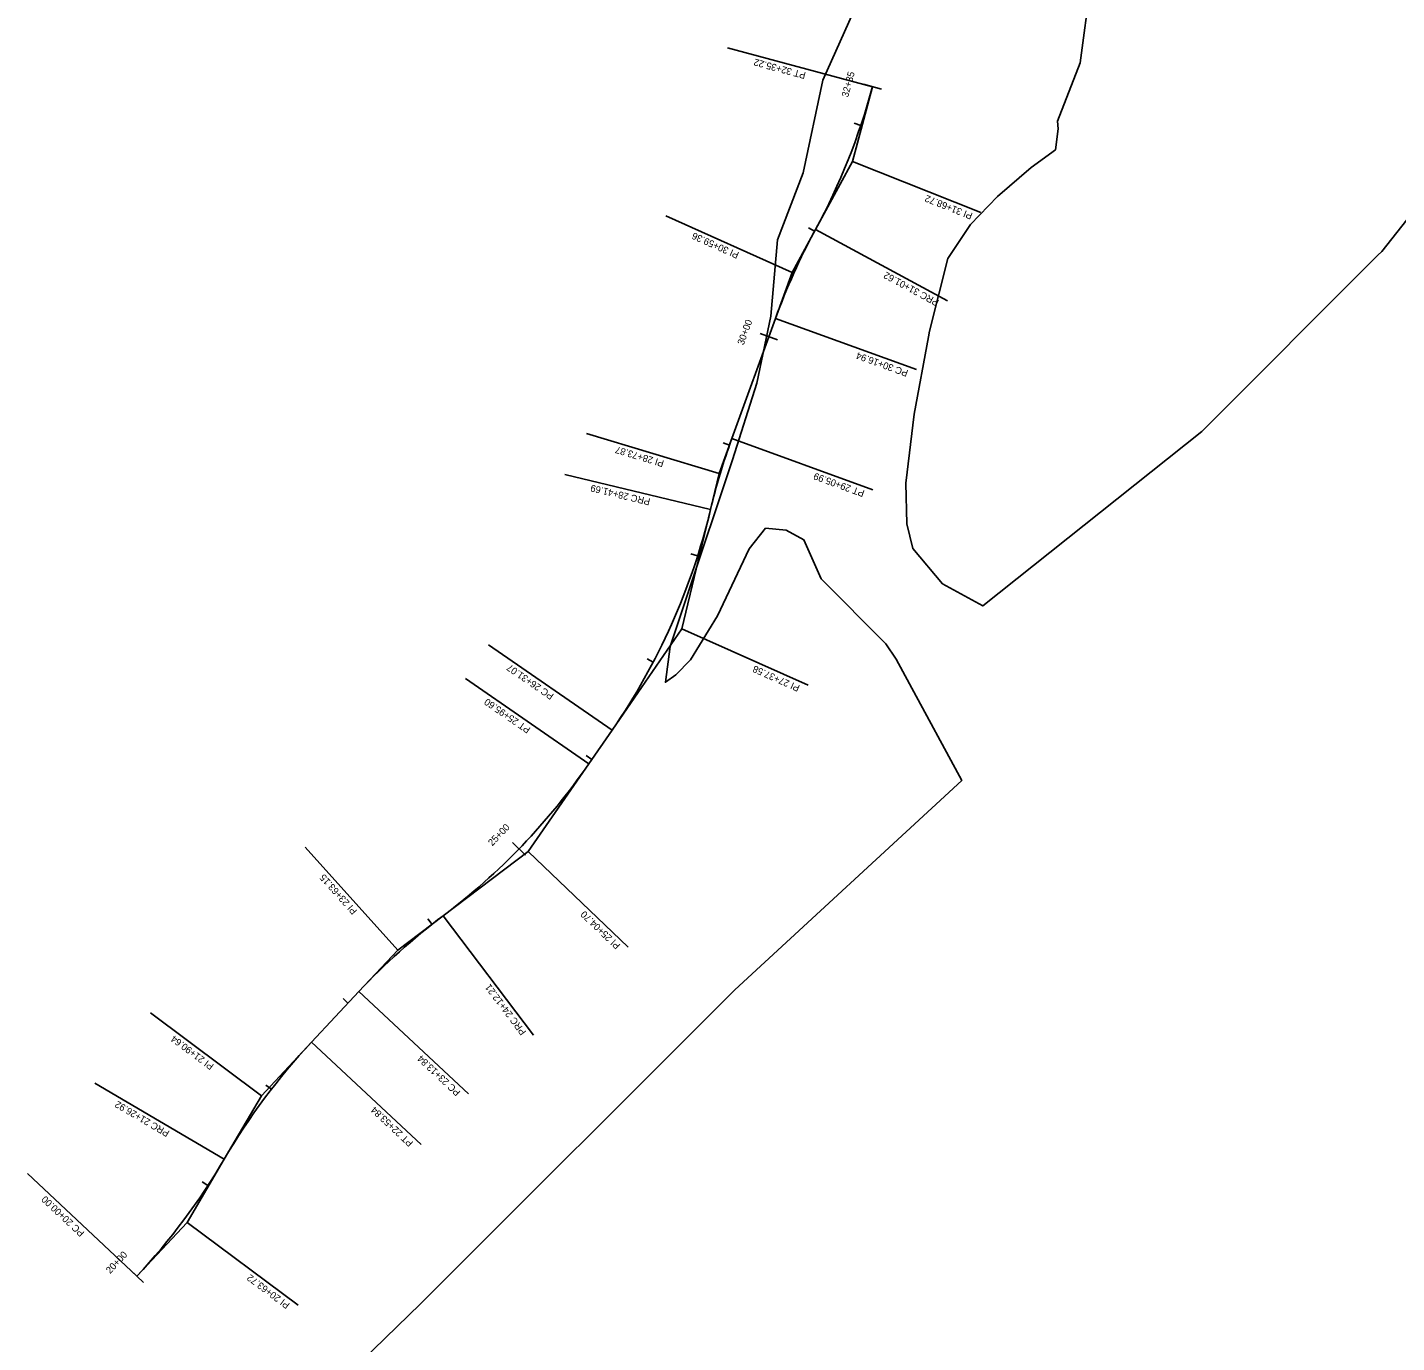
# Model space of a CAD drawing. Extents: x 983486 to 994833, y 1835619 to 1844358.
# Drawn here: x 991845 to 993032, y 1839010 to 1840151 of the extents above; entities that cross this region are included whole.
import ezdxf

# ---------------------------------------------------------------- set-up
doc = ezdxf.new("R2010")
doc.units = 0
for name, color, linetype in [('43', 7, 'Continuous'), ('R_Draft', 7, 'Continuous'), ('R_Horz Alg', 7, 'Continuous'), ('R_Horz Alg Annot', 7, 'Continuous'), ('R_Horz Alg Stationing', 7, 'Continuous')]:
    doc.layers.add(name, color=color, linetype=linetype)

msp = doc.modelspace()

# ---------------------------------------------------------------- linework, layer by layer
at = {"layer": '43'}
for points in [[(992766.6, 1840187.1), (992757.7, 1840119.8), (992738.1, 1840069.1), (992738.8, 1840062.5), (992736.3, 1840044.5), (992715.2, 1840029.1), (992686.1, 1840003.9), (992662.6, 1839979.6), (992642.9, 1839950.1), (992627, 1839887.1), (992626.3, 1839882.3), (992613.8, 1839815), (992606.7, 1839755.3), (992607.5, 1839719.9), (992612.6, 1839698.6), (992638.5, 1839667.8), (992673.3, 1839648.7), (992863.1, 1839800.1), (993015.9, 1839952.9), (993019.3, 1839956.3), (993238.9, 1840234.9)], [(991960.9, 1838824.7), (992185.8, 1839043.3), (992458.2, 1839315.8), (992655, 1839497.4), (992609.8, 1839581.3), (992598.3, 1839602.7), (992589.1, 1839615.8), (992533.3, 1839672.3), (992518.2, 1839706.1), (992502.9, 1839714.5), (992485, 1839716.3), (992470.8, 1839698.4), (992443.4, 1839640.3), (992420, 1839602), (992407.2, 1839589), (992398.2, 1839582.6), (992402.2, 1839613.6), (992416.8, 1839657), (992456.3, 1839775.5), (992477.4, 1839841.9), (992489.5, 1839900), (992495.2, 1839966.4), (992517.6, 1840024.4), (992534.5, 1840104.7), (992560.8, 1840163.5)]]:
    msp.add_lwpolyline(points, dxfattribs=at)
at = {"layer": 'R_Draft'}
msp.add_arc((992994.3, 1839598.3), 573, 160.0426, 166.473, dxfattribs=at)
at = {"layer": 'R_Horz Alg'}
for p, q in [((992455.7, 1839793.9), (992493.6, 1839898.2)), ((992331.7, 1839511.9), (992351.9, 1839541.1)), ((992091.4, 1839270.4), (992132.4, 1839314.3))]:
    msp.add_line(p, q, dxfattribs=at)
for centre, start, end in [((992024.4, 1840248.1), 331.5754, 344.9354), ((993032.2, 1839702.6), 151.5754, 160.0426), ((992994.3, 1839598.3), 160.0426, 166.473), ((991880.2, 1839866.3), 325.4117, 346.473), ((991860, 1839837.1), 307.073, 325.4117), ((992550.8, 1838922.9), 127.073, 136.9104), ((992509.8, 1838879), 136.9104, 149.6023), ((991521.4, 1839458.9), 316.9104, 329.6023)]:
    msp.add_arc(centre, 573, start, end, dxfattribs=at)
at = {"layer": 'R_Horz Alg Annot'}
for p, q in [((992560.2, 1840034.3), (992577.7, 1840099.1)), ((992528.3, 1839975.3), (992560.2, 1840034.3)), ((992508.1, 1839938), (992528.3, 1839975.3)), ((992493.6, 1839898.2), (992508.1, 1839938)), ((992444.8, 1839763.6), (992455.7, 1839793.9)), ((992437.2, 1839732.3), (992444.8, 1839763.6)), ((992412.3, 1839628.8), (992437.2, 1839732.3)), ((992351.9, 1839541.1), (992412.3, 1839628.8)), ((992279.2, 1839435.8), (992331.7, 1839511.9)), ((992205.4, 1839380), (992279.2, 1839435.8)), ((992166.1, 1839350.3), (992205.4, 1839380)), ((992132.4, 1839314.3), (992166.1, 1839350.3)), ((992047.9, 1839223.9), (992091.4, 1839270.4)), ((992015.6, 1839169), (992047.9, 1839223.9)), ((991983.4, 1839114), (992015.6, 1839169)), ((991939.9, 1839067.5), (991983.4, 1839114))]:
    msp.add_line(p, q, dxfattribs=at)
for points in [[(992577.7, 1840099.1), (992452.1, 1840132.9)], [(992560.2, 1840034.3), (992671.7, 1839989.9)], [(992508.1, 1839938), (992398.6, 1839987.2)], [(992528.3, 1839975.3), (992642.6, 1839913.5)], [(992493.6, 1839898.2), (992615.8, 1839853.8)], [(992444.8, 1839763.6), (992329.8, 1839798.2)], [(992455.7, 1839793.9), (992577.9, 1839749.5)], [(992437.2, 1839732.3), (992310.8, 1839762.7)], [(992412.3, 1839628.8), (992521.9, 1839579.9)], [(992351.9, 1839541.1), (992244.8, 1839614.9)], [(992331.7, 1839511.9), (992224.7, 1839585.7)], [(992166.1, 1839350.3), (992085.8, 1839439.5)], [(992279.2, 1839435.8), (992365.9, 1839352.8)], [(992205.4, 1839380), (992283.8, 1839276.3)], [(992132.4, 1839314.3), (992227.3, 1839225.5)], [(992047.9, 1839223.9), (991951.7, 1839295.7)], [(992091.4, 1839270.4), (992186.3, 1839181.6)], [(992015.6, 1839169), (991903.5, 1839234.7)], [(991939.9, 1839067.5), (991844.9, 1839156.3)], [(991983.4, 1839114), (992079.6, 1839042.2)]]:
    msp.add_lwpolyline(points, dxfattribs=at)
at = {"layer": 'R_Horz Alg Stationing'}
for points in [[(992569.9, 1840101.2), (992585.4, 1840097.1)], [(992569.9, 1840101.2), (992585.4, 1840097.1)], [(992561.8, 1840067.4), (992567.5, 1840065.4)], [(992522.2, 1839976.8), (992527.5, 1839973.9)], [(992480.3, 1839885), (992495.3, 1839879.5)], [(992448.1, 1839790.2), (992453.7, 1839788.2)], [(992420.3, 1839694), (992426, 1839692.2)], [(992382.2, 1839602.8), (992387.5, 1839600.1)], [(992329.3, 1839518.9), (992334.2, 1839515.5)], [(992265.4, 1839443.6), (992276.9, 1839432.5)], [(992192, 1839377.2), (992195.8, 1839372.5)], [(992118.6, 1839308.3), (992122.9, 1839304.2)], [(992051.8, 1839233.1), (992056.5, 1839229.5)], [(991996.4, 1839149.3), (992001.5, 1839146.1)], [(991934, 1839072.9), (991945.7, 1839062)]]:
    msp.add_lwpolyline(points, dxfattribs=at)

# ---------------------------------------------------------------- texts
at = {"layer": 'R_Horz Alg Annot'}
for s, rotation, p in [('PT 32+35.22', 164.9354, (992520.3, 1840111.5)), ('PI 31+68.72', 158.2554, (992665, 1839989.3)), ('PI 30+59.36', 155.809, (992462.5, 1839955.2)), ('PRC 31+01.62', 151.5754, (992635.9, 1839913.7)), ('PC 30+16.94', 160.0426, (992609.1, 1839853)), ('PI 28+73.87', 163.2578, (992397.4, 1839774.8)), ('PT 29+05.99', 160.0426, (992571.3, 1839748.7)), ('PRC 28+41.69', 166.473, (992385.4, 1839741.7)), ('PC 26+31.07', 145.4117, (992301.9, 1839571.9)), ('PI 27+37.58', 155.9423, (992515.2, 1839579.6)), ('PT 25+95.60', 145.4117, (992281.7, 1839542.7)), ('PI 23+63.15', 131.9917, (992131.3, 1839384.4)), ('PI 25+04.70', 136.2423, (992359.5, 1839354.7)), ('PRC 24+12.21', 127.073, (992277.8, 1839279.3)), ('PI 21+90.64', 143.2564, (992007.1, 1839250.6)), ('PC 23+13.84', 136.9104, (992220.9, 1839227.4)), ('PRC 21+26.92', 149.6023, (991968.7, 1839193)), ('PT 22+53.84', 136.9104, (992179.9, 1839183.5)), ('PC 20+00.00', 136.9104, (991894.9, 1839105.4)), ('PI 20+63.72', 143.2564, (992073, 1839043.4))]:
    msp.add_text(s, height=6, rotation=rotation, dxfattribs=at).set_placement(p)
at = {"layer": 'R_Horz Alg Stationing'}
for s, rotation, p in [('32+35', 74.9354, (992556.5, 1840089.6)), ('32+35', 74.9354, (992556.5, 1840089.6)), ('30+00', 70.0426, (992465.9, 1839874.6)), ('25+00', 45.8516, (992248, 1839440.1)), ('20+00', 46.9104, (991916.7, 1839069.1))]:
    msp.add_text(s, height=6, rotation=rotation, dxfattribs=at).set_placement(p)

doc.saveas('drawing.dxf')
